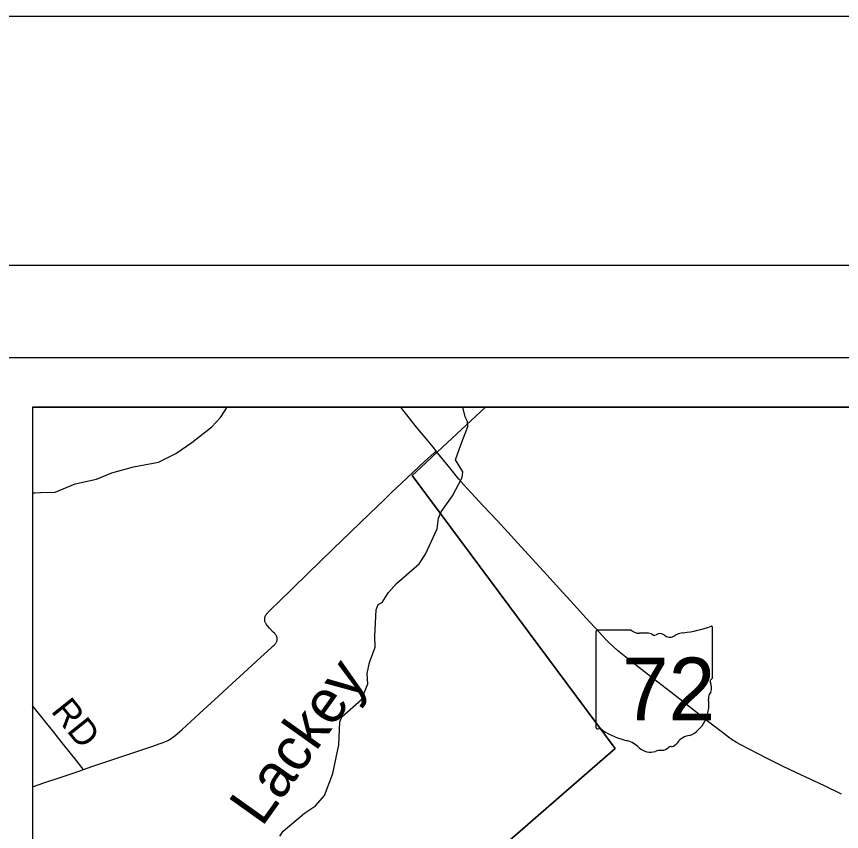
# Model space of a CAD drawing. Extents: x -13.9 to 69.1, y -25.2 to 26.1.
# Drawn here: x 1.725 to 3.383, y 20.361 to 22 of the extents above; entities that cross this region are included whole.
import ezdxf

# ---------------------------------------------------------------- set-up
doc = ezdxf.new("R2010")
doc.units = 0
for name, color, linetype in [('GM_X_Minor_River', 7, 'Continuous'), ('GM_X_Minor_River_Text', 7, 'Continuous'), ('GM_X_State_Location', 7, 'Continuous'), ('GM_X_State_Route', 7, 'Continuous'), ('GM_X_State_Shield', 7, 'Continuous'), ('GM_X_Township', 7, 'Continuous'), ('GM_X_Township_Road', 7, 'Continuous'), ('GM_X_Township_Road_Text', 7, 'Continuous'), ('SH_Border', 7, 'Continuous'), ('SH_Cut_Line', 7, 'Continuous'), ('SH_Data', 7, 'Continuous')]:
    doc.layers.add(name, color=color, linetype=linetype)

msp = doc.modelspace()

# ---------------------------------------------------------------- linework, layer by layer
at = {"layer": 'GM_X_Minor_River'}
for points in [[(1.7571, 21.0426), (1.7626, 21.0425), (1.7731, 21.0427), (1.8031, 21.0437), (1.8428, 21.0605), (1.8862, 21.07), (1.9167, 21.0822), (1.96, 21.0946), (2.0108, 21.1043), (2.0451, 21.1212), (2.0775, 21.1435), (2.1177, 21.1752), (2.1352, 21.1938), (2.1489, 21.2145)], [(2.6224, 21.0845), (2.6079, 21.1084), (2.6182, 21.1387), (2.6322, 21.1756), (2.6316, 21.1854), (2.6267, 21.1953), (2.6223, 21.2145)], [(2.2544, 20.3517), (2.261, 20.3618), (2.3043, 20.3981), (2.3261, 20.4131), (2.3443, 20.4335), (2.3608, 20.4779), (2.3702, 20.5232), (2.3734, 20.5355), (2.3751, 20.5816), (2.3793, 20.5917), (2.4186, 20.6267), (2.4312, 20.6585), (2.4301, 20.6792), (2.4348, 20.701), (2.4461, 20.732), (2.4454, 20.7542), (2.4478, 20.8072), (2.452, 20.8181), (2.4605, 20.8215), (2.4671, 20.8323), (2.4726, 20.8417), (2.489, 20.8603), (2.5345, 20.8999), (2.5476, 20.9193), (2.5706, 20.9698), (2.5736, 20.9912), (2.5785, 21.0039), (2.6015, 21.0362), (2.6209, 21.0733), (2.6224, 21.0845)]]:
    msp.add_lwpolyline(points, dxfattribs=at)
at = {"layer": 'GM_X_State_Route'}
for points in [[(2.5352, 21.1673), (2.5238, 21.1813), (2.5097, 21.1988), (2.5016, 21.2093), (2.4979, 21.2145)], [(3.3836, 20.4366), (3.3492, 20.453), (3.2915, 20.4802), (3.2663, 20.4924), (3.2351, 20.5078), (3.1967, 20.5274), (3.1812, 20.5354), (3.1725, 20.5404), (3.1639, 20.5458), (3.1561, 20.5513), (3.1444, 20.5602), (3.1198, 20.5794), (3.0651, 20.6219), (3.0522, 20.6322), (3.0401, 20.6415), (3.0056, 20.6683), (2.9635, 20.7011), (2.943, 20.7173), (2.9334, 20.7253), (2.9236, 20.734), (2.9159, 20.7415), (2.9099, 20.7477), (2.8962, 20.7624), (2.8698, 20.7912), (2.8391, 20.8246), (2.8234, 20.8422), (2.7911, 20.8772), (2.7329, 20.9408), (2.6917, 20.9857), (2.6635, 21.0159), (2.6394, 21.042), (2.6243, 21.0586), (2.6146, 21.07), (2.5959, 21.0926), (2.5687, 21.1264), (2.5637, 21.1326), (2.5472, 21.1527), (2.5352, 21.1673)]]:
    msp.add_lwpolyline(points, dxfattribs=at)
at = {"layer": 'GM_X_State_Shield'}
for p, q in [((2.8897, 20.7629), (2.8897, 20.5714)), ((2.9607, 20.7662), (2.892, 20.7662)), ((3.1242, 20.6707), (3.1242, 20.7709)), ((3.1242, 20.6708), (3.1242, 20.6707))]:
    msp.add_line(p, q, dxfattribs=at)
for centre, major_axis, start_param, end_param in [((2.8923, 20.7633), (0, 0.00292), 0.141897, 1.712693), ((2.977, 20.7884), (0, 0.0284), 2.471727, 3.160999), ((3.0407, 21.0273), (0, 0.2676), 3.243598, 3.471573), ((3.1216, 20.7714), (0, 0.00281), 4.570356, 6.418239), ((2.9858, 20.6587), (0, 0.1018), 6.117147, 6.370247), ((3.0072, 20.7643), (0, 0.00818), 2.265299, 3.614618), ((3.0184, 20.7422), (0, 0.017), 5.663012, 6.791794), ((3.0388, 20.7725), (0, 0.0205), 2.510764, 3.574926), ((3.0724, 20.7077), (0, 0.0538), 0.128215, 0.537018), ((3.1236, 20.6634), (0, 0.00435), 0.313182, 2.100276), ((3.1214, 20.6704), (0, 0.00301), 3.483744, 4.847375), ((3.0979, 20.6507), (0, 0.0261), 4.363898, 5.125152), ((3.1336, 20.6288), (0, 0.019), 0.816927, 1.691741), ((3.0546, 20.6161), (0, 0.0669), 3.530956, 4.869221), ((2.8924, 20.5709), (0, 0.00295), 1.430444, 2.937505), ((2.8928, 20.5905), (0, 0.0225), 3.095149, 3.326665), ((2.8971, 20.5603), (0, 0.00812), 5.231596, 6.340288), ((2.9923, 20.7324), (0, 0.1933), 2.625201, 2.918164), ((3.0808, 20.5176), (0, 0.0367), 0.076849, 0.917637), ((2.9387, 20.4853), (0, 0.0605), 5.535908, 6.035976), ((3.0227, 20.545), (0, 0.0204), 3.120248, 3.936577), ((3.0399, 20.5265), (0, 0.00576), 5.859973, 7.027541), ((3.0377, 20.5528), (0, 0.0216), 3.366272, 4.071454), ((2.9995, 20.5594), (0, 0.0384), 2.455685, 3.425939), ((3.0201, 20.4931), (0, 0.0315), 6.208051, 6.653369)]:
    msp.add_ellipse(centre, major_axis=major_axis, ratio=0.929448, start_param=start_param, end_param=end_param, dxfattribs=at)
at = {"layer": 'GM_X_Township'}
for points in [[(2.668, 21.2145), (1.7571, 21.2145), (1.7571, 19.5083), (2.2857, 19.9688), (2.3149, 19.9943), (2.9282, 20.5283), (2.5207, 21.0774), (2.5376, 21.0933), (2.5713, 21.1249)], [(8.0976, 21.2145), (2.668, 21.2145), (2.5713, 21.1249), (2.5376, 21.0933), (2.5207, 21.0774), (2.9282, 20.5283), (2.3149, 19.9943), (2.3345, 19.9924), (2.4186, 19.989), (2.4692, 19.987), (2.5176, 19.987), (2.5995, 20.0118), (2.5714, 18.9023), (4.5288, 18.7816), (7.8661, 18.459), (7.9988, 20.0382), (8.0428, 20.5625)]]:
    msp.add_lwpolyline(points, close=True, dxfattribs=at)
at = {"layer": 'GM_X_Township_Road'}
for points in [[(2.5234, 21.0847), (2.5453, 21.1051), (2.5647, 21.1228), (2.5687, 21.1264)], [(1.8597, 20.4861), (1.8784, 20.4925), (1.9448, 20.5151), (1.9992, 20.5332), (2.0119, 20.5374), (2.0198, 20.5402), (2.0234, 20.5417), (2.027, 20.5432), (2.0305, 20.545), (2.034, 20.5469), (2.037, 20.5489), (2.0409, 20.5517), (2.0441, 20.5542), (2.0484, 20.5577), (2.0583, 20.5664), (2.0931, 20.5986), (2.1396, 20.6417), (2.1584, 20.6591), (2.1813, 20.6798), (2.2149, 20.7107), (2.2378, 20.7313), (2.2411, 20.7344), (2.2428, 20.7361), (2.2448, 20.7382), (2.2456, 20.7393), (2.2463, 20.7403), (2.2471, 20.7415), (2.2476, 20.7424), (2.2482, 20.7435), (2.2486, 20.7447), (2.2489, 20.7458), (2.2492, 20.7469), (2.2493, 20.7479), (2.2493, 20.7488), (2.2492, 20.7499), (2.2491, 20.7508), (2.2489, 20.7517), (2.2485, 20.7526), (2.248, 20.7537), (2.2476, 20.7547), (2.247, 20.7556), (2.2463, 20.7567), (2.2452, 20.7582), (2.2441, 20.7594), (2.2413, 20.7624), (2.2337, 20.7702), (2.2302, 20.774), (2.2287, 20.7759), (2.2274, 20.7776), (2.2267, 20.7788), (2.226, 20.78), (2.2254, 20.7812), (2.225, 20.7823), (2.2246, 20.7834), (2.2244, 20.7844), (2.2242, 20.7855), (2.224, 20.787), (2.224, 20.7883), (2.2241, 20.7895), (2.2242, 20.7906), (2.2244, 20.7917), (2.2247, 20.7928), (2.2252, 20.7939), (2.2258, 20.7955), (2.2263, 20.7963), (2.2267, 20.797), (2.2276, 20.7983), (2.2284, 20.7994), (2.2295, 20.8007), (2.2306, 20.8019), (2.2318, 20.8032), (2.2379, 20.8091), (2.2518, 20.8224), (2.3101, 20.8796), (2.3619, 20.9297), (2.3959, 20.9627), (2.4355, 21.0008), (2.4626, 21.0271), (2.479, 21.043), (2.5097, 21.0721), (2.5234, 21.0847)], [(1.8597, 20.4861), (1.8565, 20.4902), (1.8476, 20.5016), (1.817, 20.5399), (1.7999, 20.561), (1.7585, 20.6129), (1.7571, 20.6147)], [(1.7571, 20.4512), (1.7819, 20.4599), (1.8131, 20.4703), (1.8411, 20.4796), (1.8597, 20.4861)]]:
    msp.add_lwpolyline(points, dxfattribs=at)
at = {"layer": 'SH_Border'}
msp.add_lwpolyline([(1.5, 21.5), (33.5, 21.5), (33.5, 0.5), (1.5, 0.5)], close=True, dxfattribs=at)
at = {"layer": 'SH_Cut_Line'}
msp.add_lwpolyline([(0, 0), (34, 0), (34, 22), (0, 22)], close=True, dxfattribs=at)
at = {"layer": 'SH_Data'}
for p, q in [((1.6571, 21.3145), (8.6571, 21.3145)), ((1.7571, 21.2145), (1.7571, 14.4145)), ((1.7571, 21.2145), (8.5571, 21.2145))]:
    msp.add_line(p, q, dxfattribs=at)

# ---------------------------------------------------------------- texts
at = {"layer": 'GM_X_Minor_River_Text'}
msp.add_text('Lackey', height=0.08666, rotation=54.5741, dxfattribs=at).set_placement((2.2186, 20.3689))
at = {"layer": 'GM_X_State_Location'}
for s in ['s', 'r']:
    msp.add_text(s, height=0.000181, dxfattribs=at).set_placement((3.0043, 20.6544))
msp.add_text('72', height=0.000181, rotation=0, dxfattribs=at).set_placement((2.9619, 20.6412))
at = {"layer": 'GM_X_State_Shield'}
msp.add_text('72', height=0.12619, dxfattribs=at).set_placement((2.9421, 20.5849))
at = {"layer": 'GM_X_Township_Road_Text'}
msp.add_text('RD', height=0.05221, rotation=308.7532, dxfattribs=at).set_placement((1.7931, 20.603))

doc.saveas('drawing.dxf')
